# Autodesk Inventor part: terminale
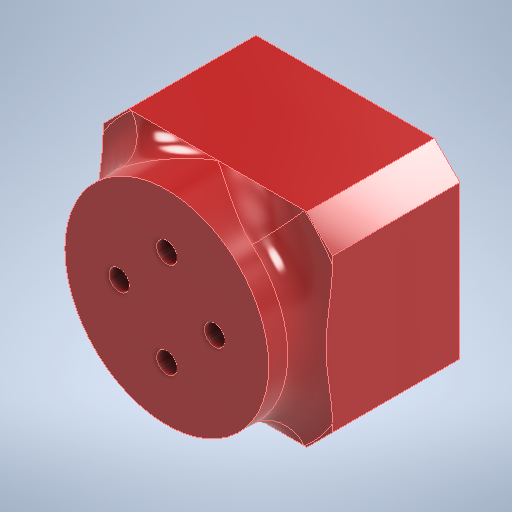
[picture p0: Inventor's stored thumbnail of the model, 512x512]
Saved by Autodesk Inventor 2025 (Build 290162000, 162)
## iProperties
Created: 2026-01
Part Number: terminale
Material: Plastica ABS
Document SubType Name: Modeling
Designer: Ryzen5700u
Density: 1.06 g/cm^3
Appearance: Rosso
Author: Ryzen5700u
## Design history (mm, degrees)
sketch "Schizzo1"
  geometry: L1 (-10.05, 10.05)-(10.05, 10.05); L2 (10.05, 10.05)-(10.05, -10.05); L3 (10.05, -10.05)-(-10.05, -10.05); L4 (-10.05, -10.05)-(-10.05, 10.05); L5 (-10.05, 10.05)-(10.05, -10.05); L6 (10.05, 10.05)-(-10.05, -10.05); L7 (-18, 16)-(18, 16); L8 (18, 16)-(18, -16); L9 (18, -16)-(-18, -16); L10 (-18, -16)-(-18, 16); L11 (-18, 16)-(18, -16); L12 (18, 16)-(-18, -16); 1 further point
  constraints: 24 end point, 4 midpoint, 4 parallel, 2 horizontal, 2 perpendicular
  dimensions: "d0" = 20.1 distance of L2.end L3.end; "d1" = 20.1 distance of L1.end L2.end; "d2" = 36 distance of L8.end L9.end; "d3" = 32 distance of L7.end L8.end
extrude "Estrusione1" new body sketch "Schizzo1" stored distance "d4" = 20; taper "d5" = 0 deg
sketch "Schizzo2"
  geometry: C1 r 16 at (0, 0); 1 further point
  constraints: 1 centre point, 1 coincident
extrude "Estrusione2" join sketch "Schizzo2" distance "d6" = 8; taper "d7" = 0 deg
fillet "Raccordo1" dims "d8" = 5
sketch "Schizzo3" dims "d9" = 15
  geometry: L1 (0, 0)-(7.5, 0); 2 further points
  constraints: 2 coincident, 2 end point, 1 horizontal, 1 horizontal alignment, 2 other
hole "Foro1" sketch "Schizzo3" at (7.5, 0) diameter "d10" = 3.2; stored, may be unused: countersink angle "d14" = 90 deg, drill point angle "d16" = 118 deg; dims "d11" = 6, "d12" = 6.5, "d13" = 3.4, "d15" = 8
sketch "Schizzo4" dims "d17" = 6.5
  geometry: L1 (10.75, 0)-(9.125, -2.815); L2 (9.125, -2.815)-(5.875, -2.815); L3 (5.875, -2.815)-(4.25, 0); L4 (4.25, 0)-(5.875, 2.815); L5 (5.875, 2.815)-(9.125, 2.815); L6 (9.125, 2.815)-(10.75, 0); C1 r 1.6 at (7.5, 0) reference; 3 further points
  constraints: 12 end point, 2 coincident, 1 horizontal alignment, 15 other
extrude "Estrusione3" cut sketch "Schizzo4" distance "d18" = 4; taper "d19" = 0 deg
sketch "Schizzo5"
  geometry: L1 (-18, -16)-(18, -16) reference; L2 (18, -16)-(18, 16) reference; L3 (18, 16)-(-18, 16) reference; L4 (-18, 16)-(-18, -16) reference; L5 (-10.05, 10.05)-(10.05, 10.05) reference; L6 (10.05, 10.05)-(10.05, -10.05) reference; L7 (10.05, -10.05)-(-10.05, -10.05) reference; L8 (-10.05, -10.05)-(-10.05, 10.05) reference; L9 (5.875, 2.815)-(9.125, 2.815) reference; L10 (4.25, 0)-(5.875, 2.815) reference; L11 (5.875, -2.815)-(4.25, 0) reference; L12 (9.125, -2.815)-(5.875, -2.815) reference; L13 (10.75, 0)-(9.125, -2.815) reference; L14 (9.125, 2.815)-(10.75, 0) reference; C1 r 1.6 at (7.5, 0) reference; 3 further points
extrude "Estrusione4" cut sketch "Schizzo5" stored distance "d20" = 0; taper "d21" = 0 deg
pattern_circular "Serie circolare1" dims "d23" = 360 deg
chamfer "Smusso1" distance "d25" = 4; stored, may be unused: second distance "d26" = 2, angle "d27" = 45 deg
node "Solido1"
node "Linea chiusa proiettata1"
node "Linea chiusa proiettata2"
